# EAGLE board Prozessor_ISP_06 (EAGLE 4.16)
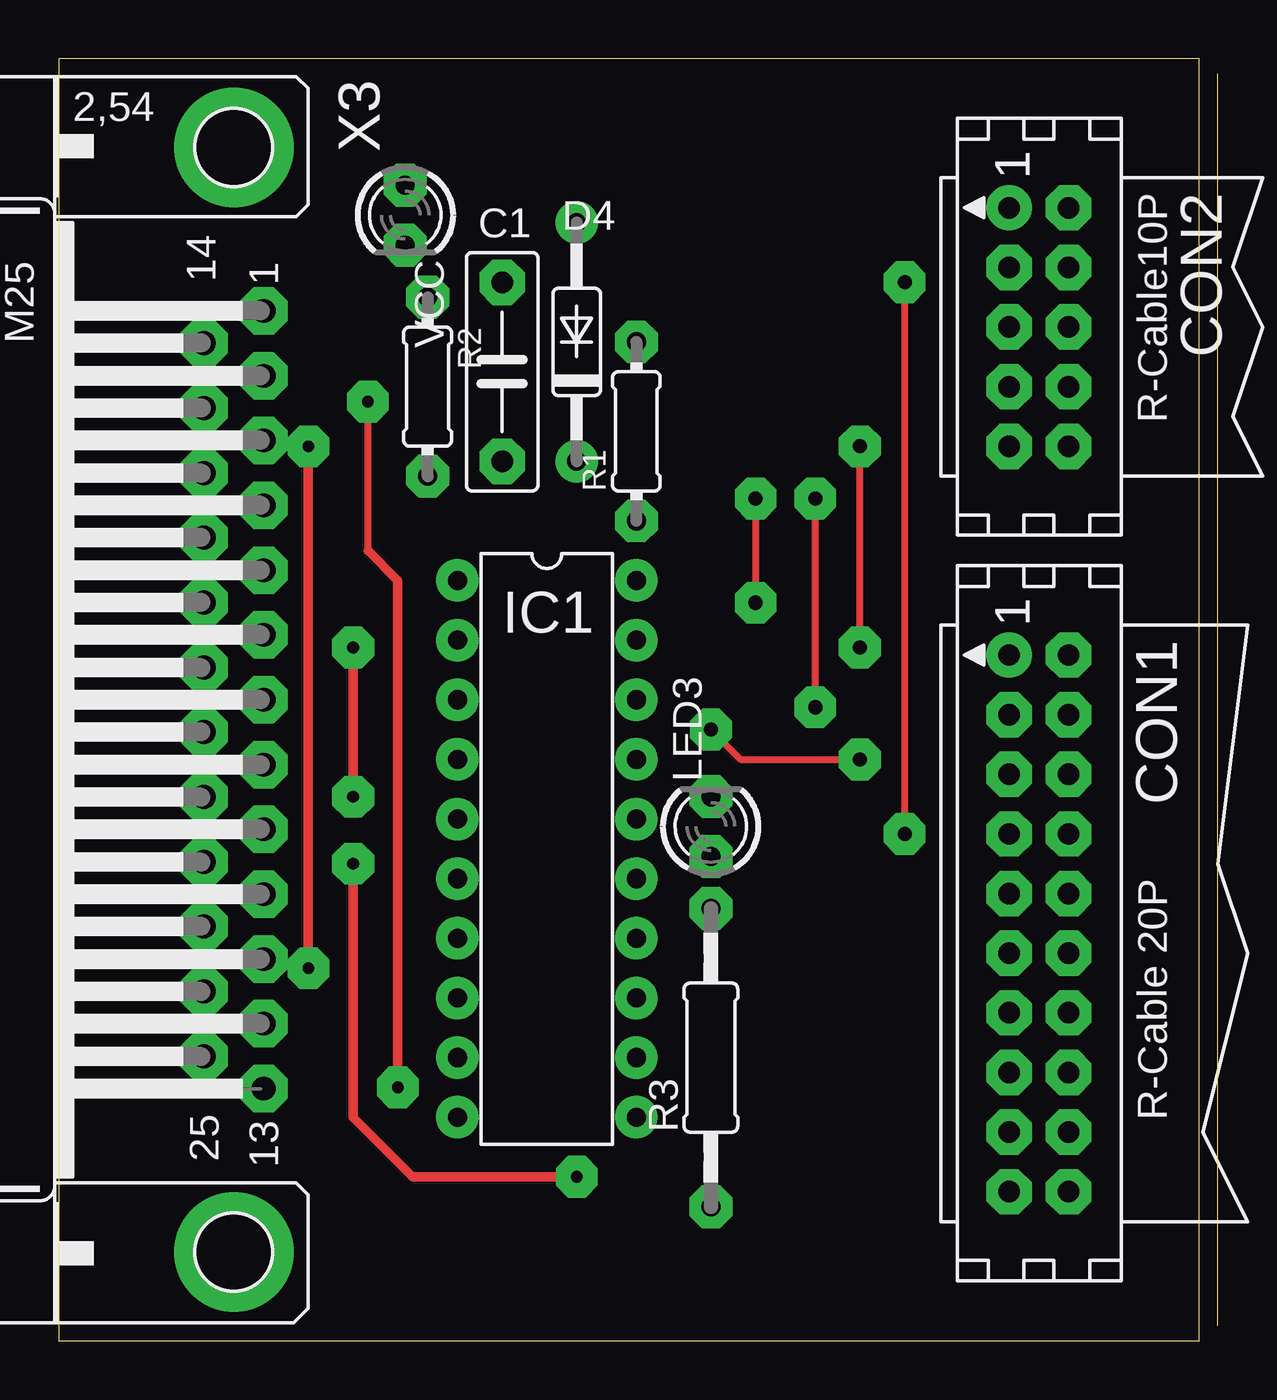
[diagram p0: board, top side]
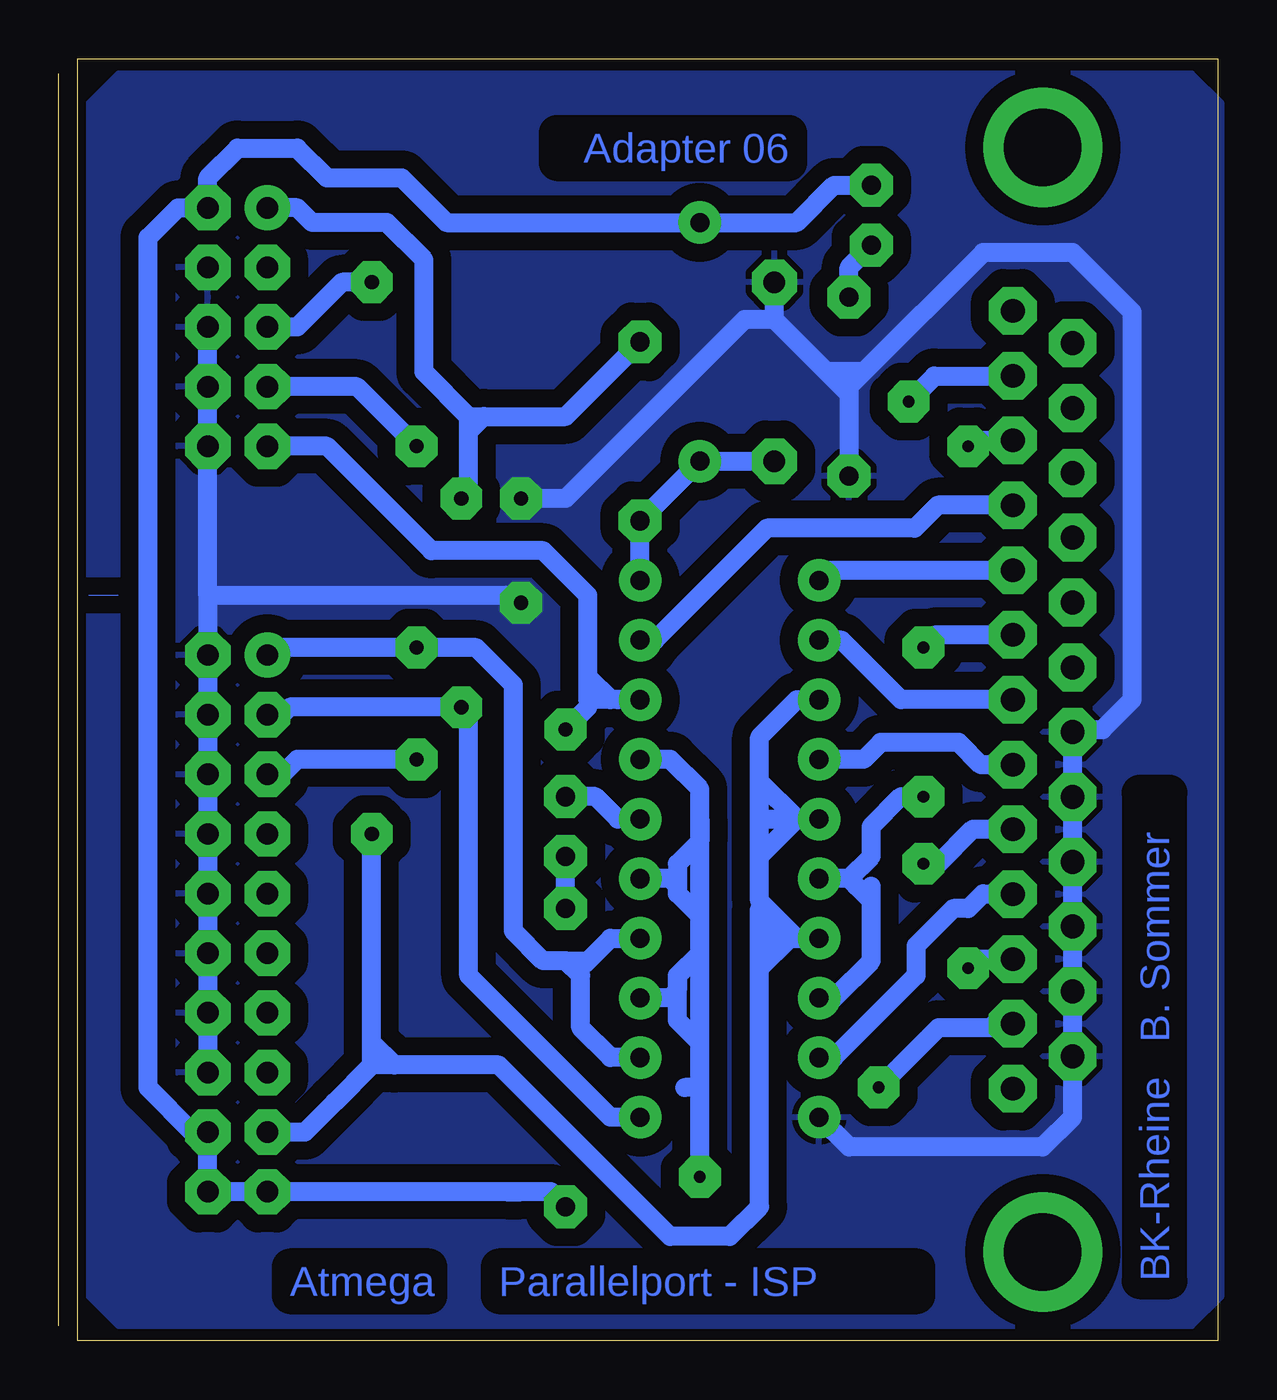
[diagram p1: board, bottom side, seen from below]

Size 49.37 x 54.6 mm. Coordinates in mm from the lower left corner, seen from the top.
Outline: 49.37,0.63 49.37,53.97
Outline: 0,0 48.56,0 48.56,54.6 0,54.6 0,0
Copper layers (1*16): Top 0.035mm / dielectric 1.5mm / Bottom 0.035mm
Design rules "sommer03": minimum track width 1mil, minimum drill 0.5mm, track to track 30mil, track to pad 30mil, pad to pad 24mil, via to via 30mil, smd to smd 8mil, copper to edge 0mil, drill to drill 8mil, minimum pad ring 20mil, minimum via ring 20mil, stop-mask expansion 4mil, vias tented up to drill 0mil, thermal gap 10mil

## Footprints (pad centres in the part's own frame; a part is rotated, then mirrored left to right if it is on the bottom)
C075-032X103 = drill 0.914 pad 1.778 octagon: 1 -3.81,0; 2 3.81,0
CON20 = drill 0.914 round: 1 -11.43,-1.27 | drill 0.914 octagon: 2 -11.43,1.27; 3 -8.89,-1.27; 4 -8.89,1.27; 5 -6.35,-1.27; 6 -6.35,1.27; 7 -3.81,-1.27; 8 -3.81,1.27; 9 -1.27,-1.27; 10 -1.27,1.27; 11 1.27,-1.27; 12 1.27,1.27; 13 3.81,-1.27; 14 3.81,1.27; 15 6.35,-1.27; 16 6.35,1.27; 17 8.89,-1.27; 18 8.89,1.27; 19 11.43,-1.27; 20 11.43,1.27
CON10 = drill 0.914 round: 1 -5.08,-1.27 | drill 0.914 octagon: 2 -5.08,1.27; 3 -2.54,-1.27; 4 -2.54,1.27; 5 0,-1.27; 6 0,1.27; 7 2.54,-1.27; 8 2.54,1.27; 9 5.08,-1.27; 10 5.08,1.27
DO35-10 = drill 0.813 long: A 5.08,0; C -5.08,0
DIL20 = drill 0.813 long: 1 -11.43,-3.81; 2 -8.89,-3.81; 3 -6.35,-3.81; 4 -3.81,-3.81; 5 -1.27,-3.81; 6 1.27,-3.81; 7 3.81,-3.81; 8 6.35,-3.81; 9 8.89,-3.81; 10 11.43,-3.81; 11 11.43,3.81; 12 8.89,3.81; 13 6.35,3.81; 14 3.81,3.81; 15 1.27,3.81; 16 -1.27,3.81; 17 -3.81,3.81; 18 -6.35,3.81; 19 -8.89,3.81; 20 -11.43,3.81
LED3MM = drill 0.813 pad 1.778 octagon: A -1.27,0; K 1.27,0
0204/7 = drill 0.813 pad 1.778 octagon: 1 -3.81,0; 2 3.81,0
0207/12 = drill 0.813 pad 1.778 octagon: 1 -6.35,0; 2 6.35,0
M25HP = drill 1.016 octagon: 1 -16.561,1.27; 2 -13.792,1.27; 3 -11.049,1.27; 4 -8.28,1.27; 5 -5.512,1.27; 6 -2.769,1.27; 7 0,1.27; 8 2.769,1.27; 9 5.512,1.27; 10 8.28,1.27; 11 11.049,1.27; 12 13.792,1.27; 13 16.561,1.27; 14 -15.189,-1.27; 15 -12.421,-1.27; 16 -9.652,-1.27; 17 -6.909,-1.27; 18 -4.14,-1.27; 19 -1.372,-1.27; 20 1.372,-1.27; 21 4.14,-1.27; 22 6.909,-1.27; 23 9.652,-1.27; 24 12.421,-1.27; 25 15.189,-1.27 | drill 3.302 pad 5.08 round: G1 -23.52,0; G2 23.52,0

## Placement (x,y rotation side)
C1  100n  [C075-032X103]  18.89,41.27 90 top
CON1  [CON20]  41.74,17.77 270 top
CON2  [CON10]  41.74,43.18 270 top
D4  1n4148  [DO35-10]  22.06,42.54 90 top
IC1  74HCT244N  [DIL20]  20.79,20.95 270 top
LED3  LED  [LED3MM]  27.78,21.9 90 top
R1  100k  [0204/7]  24.6,38.73 90 top
R2  470  [0204/7]  15.71,40.64 270 top
R3  470  [0207/12]  27.78,12.06 90 top
VCC  LED  [LED3MM]  14.76,47.94 270 top
X3  [M25HP]  7.46,27.3 270 top

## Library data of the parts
C1 R1-R3 = rcl
CON1 CON2 = con-harting
D4 = diode
IC1 = 74xx-eu
LED3 VCC = led
X3 = con-subd

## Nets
GND: C1.2 CON1.2 CON1.4 CON1.6 CON1.8 CON1.10 CON1.12 CON1.14 CON1.16 CON2.4 CON2.6 CON2.8 CON2.10 IC1.10 R2.2 X3.20 X3.21 X3.22 X3.23 X3.24 X3.25
N$2: LED3.A R3.2
N$4: R2.1 VCC.K
N$17: IC1.2 X3.7
N$19: IC1.4 X3.8
N$20: IC1.6 IC1.8 X3.6
N$21: IC1.1 X3.5
N$22: IC1.13 IC1.15 IC1.17 X3.9
N$23: IC1.9 X3.10
N$24: IC1.19 X3.4
N$25: X3.3 X3.11
N$26: X3.2 X3.12
N$28: C1.1 D4.C IC1.20 R1.1
N$32: IC1.16 LED3.K
PB5-MOSI: CON1.5 CON2.9 IC1.18
PB6-MISO: CON1.3 CON2.1 IC1.11 R1.2
PB7-SCK: CON1.1 CON2.7 IC1.12 IC1.14
RESET: CON1.17 CON2.5 IC1.3 IC1.5 IC1.7
VCC: CON1.18 CON1.19 CON1.20 CON2.2 D4.A R3.1 VCC.A

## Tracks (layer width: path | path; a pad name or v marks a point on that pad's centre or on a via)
GND  (via drill 0.6 pad 1.78)
  Top 0.305: v29.68,35.87 v29.68,31.43
  Bottom 0.813: X3.25 6.18,12.06 | X3.25 X3.24 X3.23 X3.22 X3.21 X3.20 6.18,26.03 4.92,26.03 3.65,27.3 3.65,43.81 6.18,46.35 10,46.35 15.08,41.27 | X3.25 6.18,9.52 7.46,8.25 15.71,8.25 IC1.10 | CON1.16 CON1.14 CON1.12 CON1.10 CON1.8 CON1.6 CON1.4 CON1.2 43.02,31.74 | CON2.6 CON2.8 CON2.10 43.02,31.74 | 43.02,31.74 30,31.74 v29.68,31.43 | 15.71,40.32 R2.2 | 16.66,41.27 15.71,40.32 | 16.66,41.27 18.89,43.49 | 18.89,43.49 C1.2 | 15.08,41.27 15.71,40.64 15.71,40.32 | 15.08,41.27 16.66,41.27 | 18.89,43.49 20.16,43.49 27.78,35.87 v29.68,35.87
  pour Bottom: 1.1,53.97 46.83,53.97 48.09,52.7 48.09,1.9 46.83,0.63 1.1,0.63 -0.17,1.9 -0.17,52.7
N$1
  Bottom 0: 46.83,31.74 48.09,31.74
N$2
  Bottom 0.813: R3.2 LED3.A
N$3
  pour Bottom: 1.1,52.7 46.83,52.7 46.83,1.9 1.1,1.9
N$4
  Bottom 0.813: VCC.K 15.71,45.72 R2.1
N$17
  Bottom 0.813: X3.7 13.49,27.3 16.03,29.84 IC1.2
N$19
  Bottom 0.813: X3.8 10.08,24.53 11.04,25.48 14.35,25.48 15.08,24.76 IC1.4
N$20  (via drill 0.5 pad 1.78)
  Top 0.406: v12.54,23.17 v12.54,29.52
  Bottom 0.813: IC1.8 16.35,14.6 14.76,16.19 14.76,18.41 | 14.76,18.41 14.76,18.73 15.71,19.68 | 15.71,19.68 IC1.6 | 14.76,18.41 14.76,19.36 | 15.71,19.68 15.39,19.36 | v12.54,23.17 13.49,23.17 14.76,21.9 14.76,20.63 15.71,19.68 | X3.6 11.99,30.07 v12.54,29.52
N$21
  Bottom 0.813: 16.66,32.38 IC1.1 16.55,32.81 X3.5
N$22  (via drill 0.5 pad 1.78)
  Top 0.406: v22.06,6.98 15.08,6.98 12.54,9.52 v12.54,20.31
  Bottom 0.813: 22.06,22.22 22.06,21.27 23.01,20.31 23.01,19.04 | 23.01,19.04 22.06,18.09 22.06,16.5 23.01,15.55 | X3.9 10.43,21.79 11.9,20.31 v12.54,20.31 | 23.01,15.55 23.01,13.65 22.06,12.7 22.06,12.06 | 22.06,10.79 22.06,12.06 | 22.06,12.06 22.06,22.22 | 22.06,10.79 22.7,10.79 | 22.06,22.22 22.06,23.49 23.33,24.76 IC1.17 | 23.01,15.55 23.01,14.92 23.33,14.6 IC1.13 | 23.01,19.04 23.01,19.36 23.33,19.68 IC1.15 | v22.06,6.98 22.06,10.79
N$23
  Bottom 0.813: X3.10 10.02,19.02 | 10.02,19.02 10.63,18.41 11.27,18.41 12.85,16.82 12.85,15.55 16.35,12.06 IC1.9 | 10.02,19.02 10,19.04
N$24
  Bottom 0.813: X3.4 11.93,35.58 12.9,34.6 19.2,34.6 23.96,29.84 IC1.19
N$25  (via drill 0.5 pad 1.78)
  Top 0.406: v10.63,15.87 v10.63,38.1
  Bottom 0.813: X3.11 10.25,16.25 v10.63,15.87 | X3.3 10.38,38.35 v10.63,38.1
N$26  (via drill 0.5 pad 1.78)
  Top 0.305: 13.17,33.65 v13.17,40
  Top 0.406: v14.44,10.79 14.44,32.38 13.17,33.65
  Bottom 0.813: X3.2 12.08,41.09 v13.17,40 | X3.12 9.5,13.51 9.68,13.33 11.9,13.33 v14.44,10.79
N$28
  Bottom 0.813: IC1.20 R1.1 D4.C C1.1
N$32
  Bottom 0.813: IC1.16 25.55,22.22 26.51,23.17 LED3.K
PB5-MOSI  (via drill 0.6 pad 1.78)
  Top 0.305: v34.12,24.76 29.05,24.76 v27.78,26.03
  Bottom 0.813: v34.12,24.76 39.2,24.76 39.84,24.12 CON1.5 | IC1.18 25.55,27.3 | 25.55,27.3 25.87,27.3 26.82,28.25 | 26.82,28.25 26.82,31.74 28.73,33.65 33.49,33.65 37.94,38.1 CON2.9 | v27.78,26.03 26.82,26.98 26.82,27.3 | 26.82,27.3 26.82,28.25 | 25.55,27.3 26.82,27.3
PB6-MISO  (via drill 0.6 pad 1.78)
  Top 0.305: v32.22,26.98 v32.22,35.87
  Bottom 0.813: IC1.11 25.87,9.52 31.9,15.55 31.9,26.66 v32.22,26.98 39.52,26.98 39.84,26.66 CON1.3 | CON2.1 39.2,48.26 38.57,47.62 35.4,47.62 33.81,46.03 33.81,41.27 31.9,39.37 | v32.22,35.87 31.9,36.19 31.9,38.73 | 31.9,38.73 31.9,39.37 | R1.2 27.78,39.37 31.27,39.37 | 31.9,39.37 31.27,39.37 | 31.9,38.73 31.27,39.37
PB7-SCK  (via drill 0.6 pad 1.78)
  Top 0.305: v34.12,29.52 v34.12,38.1
  Bottom 0.813: IC1.12 25.87,12.06 27.14,13.33 27.14,15.55 | 27.14,15.55 27.14,15.87 26.82,16.19 | 26.82,16.19 25.87,17.14 IC1.14 | 27.78,16.19 26.82,16.19 | 27.78,16.19 28.73,16.19 30,17.46 30,27.93 31.59,29.52 v34.12,29.52 40.16,29.52 CON1.1 | 27.14,15.55 27.78,16.19 | CON2.7 36.66,40.64 v34.12,38.1
RESET  (via drill 0.6 pad 1.78)
  Top 0.305: v36.03,21.58 v36.03,45.08
  Bottom 0.813: IC1.3 17.93,27.3 19.52,25.71 19.52,23.81 | 17.93,22.22 19.52,23.81 | 17.93,22.22 IC1.5 | 19.52,20.63 17.93,22.22 | 19.52,20.63 19.52,18.73 17.93,17.14 | 17.93,17.14 IC1.7 | 19.52,20.63 19.52,22.22 | 19.52,22.22 19.52,23.81 | 19.52,22.22 18.25,22.22 | 18.25,17.14 17.93,17.14 | 18.25,17.14 19.52,15.87 19.52,17.14 | 19.52,17.14 19.52,18.41 18.25,17.14 | 19.52,17.14 18.25,17.14 | 19.52,17.14 19.52,5.71 20.79,4.44 23.33,4.44 30.63,11.74 35.08,11.74 | v36.03,45.08 37.3,45.08 39.2,43.18 CON2.5 | 37.62,10.16 37.3,10.47 | 37.62,10.16 38.89,8.89 CON1.17 | 36.03,11.74 36.03,12.7 | 36.03,12.7 v36.03,21.58 | 36.03,11.74 37.62,10.16 | 35.08,11.74 36.03,11.74 | 35.08,11.74 36.03,12.7
VCC
  Bottom 0.813: 30.32,6.34 29.68,6.34 | VCC.A 16.35,49.21 17.93,47.62 D4.A 32.86,47.62 34.76,49.53 37.94,49.53 39.2,50.8 41.74,50.8 43.02,49.53 CON2.2 44.29,48.26 45.55,46.98 45.55,10.79 43.65,8.89 CON1.18 CON1.20 CON1.19 30.32,6.34 | R3.1 28.41,6.34 30.32,6.34

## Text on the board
Bottom: Adapter 06 | BK-Rheine B. Sommer | Parallelport - ISP | Atmega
